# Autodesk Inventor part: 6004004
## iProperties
Category: PARTsolutions
Created: 2007-09
Part Number: 6004004
Catalog Web Link: www.cadenas.de
Description: Series 6004,6004-MM_link - Straight Line Action Clamps
Document SubType Name: Modeling
Designer: PARTsolutions
Material: 1.0037 St 37-2
NB: 6004004
NN: Series 6004,6004-MM_link
NT: Straight Line Action Clamps
NBSYN: $PN.
LINA: 6004004
PN: 6004004
A1: 1.250
A2: 0.500
A3: 0.120
A4: 0.500
A5: 0.185
D1: 0.189
ANG1: 31
R1: 0.190
R2: 0.145
R3: 0.230
R4: 0.640
R5: 0.250
KT: DUMMY
PSOL_IDENT_0: {\\partserver001.servicenet\dplatte\cadenas\23d-libs\destaco\industries\manual_clamps\straight_line_
PSOL_IDENT_1: action_clamps\through_hole_mount\6004_parts\6004_link.prj},165 {VTYP=3D},{NB=6004004},{LINA=6004004}
PSOL_IDENT_2: ,{NN=Series 6004,6004-MM_link},{DATE=19.06.2006 12:58:53},{GEOMDATE=19.06.2006},{VERSION=},{LINEID=1
PSOL_IDENT_3: 0},{LINESUBID=-1},{WBVAR=}  {NB=6004004},{LINA=6004004},{KT=DUMMY},{PN=6004004},{A1=1.250},{A2=0.500
PSOL_IDENT_4: },{A3=0.120},{A4=0.500},{A5=0.185},{D1=0.189},{ANG1=31},{R1=0.190},{R2=0.145},{R3=0.230},{R4=0.640},
PSOL_IDENT_5: {R5=0.250}
Title: 6004004
Author: Cadenas PARTsolutions
Comments: Straight Line Action Clamps
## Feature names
1. Extrusion1
